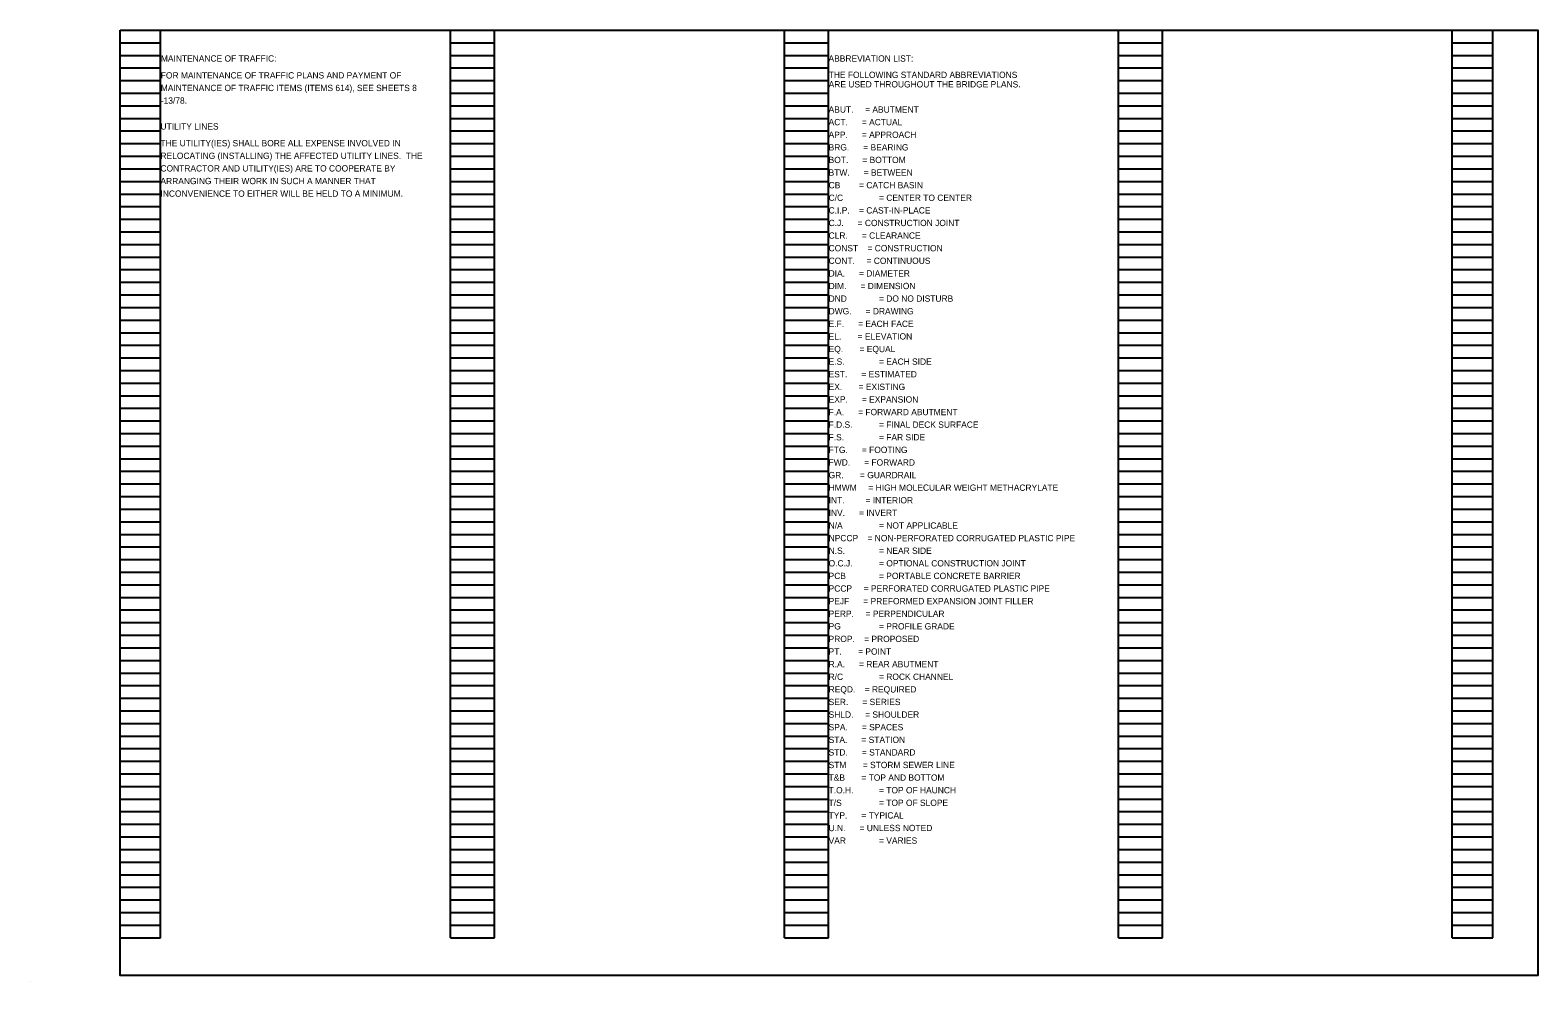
# Model space of a CAD drawing. Extents: x 8.9 to 72, y -18.6 to 3.4.
# Drawn here: x 8.86 to 42.36, y -18.57 to 2.57 of the extents above; entities that cross this region are included whole.
import ezdxf

# ---------------------------------------------------------------- set-up
doc = ezdxf.new("R2010")
doc.units = 0
for name, color, linetype in [('BR_P_Gen_Text', 7, 'Continuous'), ('Default', 7, 'Continuous'), ('SC_Scratch1', 7, 'Continuous'), ('SH_Data', 7, 'Continuous')]:
    doc.layers.add(name, color=color, linetype=linetype)

msp = doc.modelspace()

# ---------------------------------------------------------------- linework, layer by layer
at = {"layer": 'SC_Scratch1'}
msp.add_lwpolyline([(10.858, 2.575), (42.358, 2.575), (42.358, -18.425), (10.858, -18.425)], close=True, dxfattribs=at)
at = {"layer": 'SH_Data'}
for p, q in [((10.858, -17.585), (10.858, 2.575)), ((10.858, 2.575), (11.758, 2.575)), ((11.758, -17.585), (11.758, 2.575)), ((18.198, -17.585), (18.198, 2.575)), ((18.198, 2.575), (19.178, 2.575)), ((19.178, -17.585), (19.178, 2.575)), ((25.618, -17.585), (25.618, 2.575)), ((25.618, 2.575), (26.598, 2.575)), ((26.598, -17.585), (26.598, 2.575)), ((33.038, -17.585), (33.038, 2.575)), ((33.038, 2.575), (34.018, 2.575)), ((34.018, -17.585), (34.018, 2.575)), ((40.458, -17.585), (40.458, 2.575)), ((40.458, 2.575), (41.358, 2.575)), ((41.358, -17.585), (41.358, 2.575)), ((10.858, 2.295), (11.758, 2.295)), ((10.858, 2.015), (11.758, 2.015)), ((18.198, 2.295), (19.178, 2.295)), ((18.198, 2.015), (19.178, 2.015)), ((25.618, 2.295), (26.598, 2.295)), ((25.618, 2.015), (26.598, 2.015)), ((33.038, 2.295), (34.018, 2.295)), ((33.038, 2.015), (34.018, 2.015)), ((40.458, 2.295), (41.358, 2.295)), ((40.458, 2.015), (41.358, 2.015)), ((10.858, 1.735), (11.758, 1.735)), ((18.198, 1.735), (19.178, 1.735)), ((25.618, 1.735), (26.598, 1.735)), ((33.038, 1.735), (34.018, 1.735)), ((40.458, 1.735), (41.358, 1.735)), ((10.858, 1.455), (11.758, 1.455)), ((18.198, 1.455), (19.178, 1.455)), ((25.618, 1.455), (26.598, 1.455)), ((33.038, 1.455), (34.018, 1.455)), ((40.458, 1.455), (41.358, 1.455)), ((10.858, 1.175), (11.758, 1.175)), ((18.198, 1.175), (19.178, 1.175)), ((25.618, 1.175), (26.598, 1.175)), ((33.038, 1.175), (34.018, 1.175)), ((40.458, 1.175), (41.358, 1.175)), ((10.858, 0.895), (11.758, 0.895)), ((18.198, 0.895), (19.178, 0.895)), ((25.618, 0.895), (26.598, 0.895)), ((33.038, 0.895), (34.018, 0.895)), ((40.458, 0.895), (41.358, 0.895)), ((10.858, 0.615), (11.758, 0.615)), ((18.198, 0.615), (19.178, 0.615)), ((25.618, 0.615), (26.598, 0.615)), ((33.038, 0.615), (34.018, 0.615)), ((40.458, 0.615), (41.358, 0.615)), ((10.858, 0.335), (11.758, 0.335)), ((10.858, 0.055), (11.758, 0.055)), ((18.198, 0.335), (19.178, 0.335)), ((18.198, 0.055), (19.178, 0.055)), ((25.618, 0.335), (26.598, 0.335)), ((25.618, 0.055), (26.598, 0.055)), ((33.038, 0.335), (34.018, 0.335)), ((33.038, 0.055), (34.018, 0.055)), ((40.458, 0.335), (41.358, 0.335)), ((40.458, 0.055), (41.358, 0.055)), ((10.858, -0.225), (11.758, -0.225)), ((18.198, -0.225), (19.178, -0.225)), ((25.618, -0.225), (26.598, -0.225)), ((33.038, -0.225), (34.018, -0.225)), ((40.458, -0.225), (41.358, -0.225)), ((10.858, -0.505), (11.758, -0.505)), ((18.198, -0.505), (19.178, -0.505)), ((25.618, -0.505), (26.598, -0.505)), ((33.038, -0.505), (34.018, -0.505)), ((40.458, -0.505), (41.358, -0.505)), ((10.858, -0.785), (11.758, -0.785)), ((18.198, -0.785), (19.178, -0.785)), ((25.618, -0.785), (26.598, -0.785)), ((33.038, -0.785), (34.018, -0.785)), ((40.458, -0.785), (41.358, -0.785)), ((10.858, -1.065), (11.758, -1.065)), ((18.198, -1.065), (19.178, -1.065)), ((25.618, -1.065), (26.598, -1.065)), ((33.038, -1.065), (34.018, -1.065)), ((40.458, -1.065), (41.358, -1.065)), ((10.858, -1.345), (11.758, -1.345)), ((10.858, -1.625), (11.758, -1.625)), ((18.198, -1.345), (19.178, -1.345)), ((18.198, -1.625), (19.178, -1.625)), ((25.618, -1.345), (26.598, -1.345)), ((25.618, -1.625), (26.598, -1.625)), ((33.038, -1.345), (34.018, -1.345)), ((33.038, -1.625), (34.018, -1.625)), ((40.458, -1.345), (41.358, -1.345)), ((40.458, -1.625), (41.358, -1.625)), ((10.858, -1.905), (11.758, -1.905)), ((18.198, -1.905), (19.178, -1.905)), ((25.618, -1.905), (26.598, -1.905)), ((33.038, -1.905), (34.018, -1.905)), ((40.458, -1.905), (41.358, -1.905)), ((10.858, -2.185), (11.758, -2.185)), ((18.198, -2.185), (19.178, -2.185)), ((25.618, -2.185), (26.598, -2.185)), ((33.038, -2.185), (34.018, -2.185)), ((40.458, -2.185), (41.358, -2.185)), ((10.858, -2.465), (11.758, -2.465)), ((18.198, -2.465), (19.178, -2.465)), ((25.618, -2.465), (26.598, -2.465)), ((33.038, -2.465), (34.018, -2.465)), ((40.458, -2.465), (41.358, -2.465)), ((10.858, -2.745), (11.758, -2.745)), ((18.198, -2.745), (19.178, -2.745)), ((25.618, -2.745), (26.598, -2.745)), ((33.038, -2.745), (34.018, -2.745)), ((40.458, -2.745), (41.358, -2.745)), ((10.858, -3.025), (11.758, -3.025)), ((10.858, -3.305), (11.758, -3.305)), ((18.198, -3.025), (19.178, -3.025)), ((18.198, -3.305), (19.178, -3.305)), ((25.618, -3.025), (26.598, -3.025)), ((25.618, -3.305), (26.598, -3.305)), ((33.038, -3.025), (34.018, -3.025)), ((33.038, -3.305), (34.018, -3.305)), ((40.458, -3.025), (41.358, -3.025)), ((40.458, -3.305), (41.358, -3.305)), ((10.858, -3.585), (11.758, -3.585)), ((18.198, -3.585), (19.178, -3.585)), ((25.618, -3.585), (26.598, -3.585)), ((33.038, -3.585), (34.018, -3.585)), ((40.458, -3.585), (41.358, -3.585)), ((10.858, -3.865), (11.758, -3.865)), ((18.198, -3.865), (19.178, -3.865)), ((25.618, -3.865), (26.598, -3.865)), ((33.038, -3.865), (34.018, -3.865)), ((40.458, -3.865), (41.358, -3.865)), ((10.858, -4.145), (11.758, -4.145)), ((18.198, -4.145), (19.178, -4.145)), ((25.618, -4.145), (26.598, -4.145)), ((33.038, -4.145), (34.018, -4.145)), ((40.458, -4.145), (41.358, -4.145)), ((10.858, -4.425), (11.758, -4.425)), ((18.198, -4.425), (19.178, -4.425)), ((25.618, -4.425), (26.598, -4.425)), ((33.038, -4.425), (34.018, -4.425)), ((40.458, -4.425), (41.358, -4.425)), ((10.858, -4.705), (11.758, -4.705)), ((10.858, -4.985), (11.758, -4.985)), ((18.198, -4.705), (19.178, -4.705)), ((18.198, -4.985), (19.178, -4.985)), ((25.618, -4.705), (26.598, -4.705)), ((25.618, -4.985), (26.598, -4.985)), ((33.038, -4.705), (34.018, -4.705)), ((33.038, -4.985), (34.018, -4.985)), ((40.458, -4.705), (41.358, -4.705)), ((40.458, -4.985), (41.358, -4.985)), ((10.858, -5.265), (11.758, -5.265)), ((18.198, -5.265), (19.178, -5.265)), ((25.618, -5.265), (26.598, -5.265)), ((33.038, -5.265), (34.018, -5.265)), ((40.458, -5.265), (41.358, -5.265)), ((10.858, -5.545), (11.758, -5.545)), ((18.198, -5.545), (19.178, -5.545)), ((25.618, -5.545), (26.598, -5.545)), ((33.038, -5.545), (34.018, -5.545)), ((40.458, -5.545), (41.358, -5.545)), ((10.858, -5.825), (11.758, -5.825)), ((18.198, -5.825), (19.178, -5.825)), ((25.618, -5.825), (26.598, -5.825)), ((33.038, -5.825), (34.018, -5.825)), ((40.458, -5.825), (41.358, -5.825)), ((10.858, -6.105), (11.758, -6.105)), ((18.198, -6.105), (19.178, -6.105)), ((25.618, -6.105), (26.598, -6.105)), ((33.038, -6.105), (34.018, -6.105)), ((40.458, -6.105), (41.358, -6.105)), ((10.858, -6.385), (11.758, -6.385)), ((10.858, -6.665), (11.758, -6.665)), ((18.198, -6.385), (19.178, -6.385)), ((18.198, -6.665), (19.178, -6.665)), ((25.618, -6.385), (26.598, -6.385)), ((25.618, -6.665), (26.598, -6.665)), ((33.038, -6.385), (34.018, -6.385)), ((33.038, -6.665), (34.018, -6.665)), ((40.458, -6.385), (41.358, -6.385)), ((40.458, -6.665), (41.358, -6.665)), ((10.858, -6.945), (11.758, -6.945)), ((18.198, -6.945), (19.178, -6.945)), ((25.618, -6.945), (26.598, -6.945)), ((33.038, -6.945), (34.018, -6.945)), ((40.458, -6.945), (41.358, -6.945)), ((10.858, -7.225), (11.758, -7.225)), ((18.198, -7.225), (19.178, -7.225)), ((25.618, -7.225), (26.598, -7.225)), ((33.038, -7.225), (34.018, -7.225)), ((40.458, -7.225), (41.358, -7.225)), ((10.858, -7.505), (11.758, -7.505)), ((18.198, -7.505), (19.178, -7.505)), ((25.618, -7.505), (26.598, -7.505)), ((33.038, -7.505), (34.018, -7.505)), ((40.458, -7.505), (41.358, -7.505)), ((10.858, -7.785), (11.758, -7.785)), ((18.198, -7.785), (19.178, -7.785)), ((25.618, -7.785), (26.598, -7.785)), ((33.038, -7.785), (34.018, -7.785)), ((40.458, -7.785), (41.358, -7.785)), ((10.858, -8.065), (11.758, -8.065)), ((10.858, -8.345), (11.758, -8.345)), ((18.198, -8.065), (19.178, -8.065)), ((18.198, -8.345), (19.178, -8.345)), ((25.618, -8.065), (26.598, -8.065)), ((25.618, -8.345), (26.598, -8.345)), ((33.038, -8.065), (34.018, -8.065)), ((33.038, -8.345), (34.018, -8.345)), ((40.458, -8.065), (41.358, -8.065)), ((40.458, -8.345), (41.358, -8.345)), ((10.858, -8.625), (11.758, -8.625)), ((18.198, -8.625), (19.178, -8.625)), ((25.618, -8.625), (26.598, -8.625)), ((33.038, -8.625), (34.018, -8.625)), ((40.458, -8.625), (41.358, -8.625)), ((10.858, -8.905), (11.758, -8.905)), ((18.198, -8.905), (19.178, -8.905)), ((25.618, -8.905), (26.598, -8.905)), ((33.038, -8.905), (34.018, -8.905)), ((40.458, -8.905), (41.358, -8.905)), ((10.858, -9.185), (11.758, -9.185)), ((18.198, -9.185), (19.178, -9.185)), ((25.618, -9.185), (26.598, -9.185)), ((33.038, -9.185), (34.018, -9.185)), ((40.458, -9.185), (41.358, -9.185)), ((10.858, -9.465), (11.758, -9.465)), ((18.198, -9.465), (19.178, -9.465)), ((25.618, -9.465), (26.598, -9.465)), ((33.038, -9.465), (34.018, -9.465)), ((40.458, -9.465), (41.358, -9.465)), ((10.858, -9.745), (11.758, -9.745)), ((10.858, -10.025), (11.758, -10.025)), ((18.198, -9.745), (19.178, -9.745)), ((18.198, -10.025), (19.178, -10.025)), ((25.618, -9.745), (26.598, -9.745)), ((25.618, -10.025), (26.598, -10.025)), ((33.038, -9.745), (34.018, -9.745)), ((33.038, -10.025), (34.018, -10.025)), ((40.458, -9.745), (41.358, -9.745)), ((40.458, -10.025), (41.358, -10.025)), ((10.858, -10.305), (11.758, -10.305)), ((18.198, -10.305), (19.178, -10.305)), ((25.618, -10.305), (26.598, -10.305)), ((33.038, -10.305), (34.018, -10.305)), ((40.458, -10.305), (41.358, -10.305)), ((10.858, -10.585), (11.758, -10.585)), ((18.198, -10.585), (19.178, -10.585)), ((25.618, -10.585), (26.598, -10.585)), ((33.038, -10.585), (34.018, -10.585)), ((40.458, -10.585), (41.358, -10.585)), ((10.858, -10.865), (11.758, -10.865)), ((18.198, -10.865), (19.178, -10.865)), ((25.618, -10.865), (26.598, -10.865)), ((33.038, -10.865), (34.018, -10.865)), ((40.458, -10.865), (41.358, -10.865)), ((10.858, -11.145), (11.758, -11.145)), ((18.198, -11.145), (19.178, -11.145)), ((25.618, -11.145), (26.598, -11.145)), ((33.038, -11.145), (34.018, -11.145)), ((40.458, -11.145), (41.358, -11.145)), ((10.858, -11.425), (11.758, -11.425)), ((10.858, -11.705), (11.758, -11.705)), ((18.198, -11.425), (19.178, -11.425)), ((18.198, -11.705), (19.178, -11.705)), ((25.618, -11.425), (26.598, -11.425)), ((25.618, -11.705), (26.598, -11.705)), ((33.038, -11.425), (34.018, -11.425)), ((33.038, -11.705), (34.018, -11.705)), ((40.458, -11.425), (41.358, -11.425)), ((40.458, -11.705), (41.358, -11.705)), ((10.858, -11.985), (11.758, -11.985)), ((18.198, -11.985), (19.178, -11.985)), ((25.618, -11.985), (26.598, -11.985)), ((33.038, -11.985), (34.018, -11.985)), ((40.458, -11.985), (41.358, -11.985)), ((10.858, -12.265), (11.758, -12.265)), ((18.198, -12.265), (19.178, -12.265)), ((25.618, -12.265), (26.598, -12.265)), ((33.038, -12.265), (34.018, -12.265)), ((40.458, -12.265), (41.358, -12.265)), ((10.858, -12.545), (11.758, -12.545)), ((18.198, -12.545), (19.178, -12.545)), ((25.618, -12.545), (26.598, -12.545)), ((33.038, -12.545), (34.018, -12.545)), ((40.458, -12.545), (41.358, -12.545)), ((10.858, -12.825), (11.758, -12.825)), ((18.198, -12.825), (19.178, -12.825)), ((25.618, -12.825), (26.598, -12.825)), ((33.038, -12.825), (34.018, -12.825)), ((40.458, -12.825), (41.358, -12.825)), ((10.858, -13.105), (11.758, -13.105)), ((10.858, -13.385), (11.758, -13.385)), ((18.198, -13.105), (19.178, -13.105)), ((18.198, -13.385), (19.178, -13.385)), ((25.618, -13.105), (26.598, -13.105)), ((25.618, -13.385), (26.598, -13.385)), ((33.038, -13.105), (34.018, -13.105)), ((33.038, -13.385), (34.018, -13.385)), ((40.458, -13.105), (41.358, -13.105)), ((40.458, -13.385), (41.358, -13.385)), ((10.858, -13.665), (11.758, -13.665)), ((18.198, -13.665), (19.178, -13.665)), ((25.618, -13.665), (26.598, -13.665)), ((33.038, -13.665), (34.018, -13.665)), ((40.458, -13.665), (41.358, -13.665)), ((10.858, -13.945), (11.758, -13.945)), ((18.198, -13.945), (19.178, -13.945)), ((25.618, -13.945), (26.598, -13.945)), ((33.038, -13.945), (34.018, -13.945)), ((40.458, -13.945), (41.358, -13.945)), ((10.858, -14.225), (11.758, -14.225)), ((18.198, -14.225), (19.178, -14.225)), ((25.618, -14.225), (26.598, -14.225)), ((33.038, -14.225), (34.018, -14.225)), ((40.458, -14.225), (41.358, -14.225)), ((10.858, -14.505), (11.758, -14.505)), ((18.198, -14.505), (19.178, -14.505)), ((25.618, -14.505), (26.598, -14.505)), ((33.038, -14.505), (34.018, -14.505)), ((40.458, -14.505), (41.358, -14.505)), ((10.858, -14.785), (11.758, -14.785)), ((10.858, -15.065), (11.758, -15.065)), ((18.198, -14.785), (19.178, -14.785)), ((18.198, -15.065), (19.178, -15.065)), ((25.618, -14.785), (26.598, -14.785)), ((25.618, -15.065), (26.598, -15.065)), ((33.038, -14.785), (34.018, -14.785)), ((33.038, -15.065), (34.018, -15.065)), ((40.458, -14.785), (41.358, -14.785)), ((40.458, -15.065), (41.358, -15.065)), ((10.858, -15.345), (11.758, -15.345)), ((18.198, -15.345), (19.178, -15.345)), ((25.618, -15.345), (26.598, -15.345)), ((33.038, -15.345), (34.018, -15.345)), ((40.458, -15.345), (41.358, -15.345)), ((10.858, -15.625), (11.758, -15.625)), ((18.198, -15.625), (19.178, -15.625)), ((25.618, -15.625), (26.598, -15.625)), ((33.038, -15.625), (34.018, -15.625)), ((40.458, -15.625), (41.358, -15.625)), ((10.858, -15.905), (11.758, -15.905)), ((18.198, -15.905), (19.178, -15.905)), ((25.618, -15.905), (26.598, -15.905)), ((33.038, -15.905), (34.018, -15.905)), ((40.458, -15.905), (41.358, -15.905)), ((10.858, -16.185), (11.758, -16.185)), ((18.198, -16.185), (19.178, -16.185)), ((25.618, -16.185), (26.598, -16.185)), ((33.038, -16.185), (34.018, -16.185)), ((40.458, -16.185), (41.358, -16.185)), ((10.858, -16.465), (11.758, -16.465)), ((10.858, -16.745), (11.758, -16.745)), ((18.198, -16.465), (19.178, -16.465)), ((18.198, -16.745), (19.178, -16.745)), ((25.618, -16.465), (26.598, -16.465)), ((25.618, -16.745), (26.598, -16.745)), ((33.038, -16.465), (34.018, -16.465)), ((33.038, -16.745), (34.018, -16.745)), ((40.458, -16.465), (41.358, -16.465)), ((40.458, -16.745), (41.358, -16.745)), ((10.858, -17.025), (11.758, -17.025)), ((18.198, -17.025), (19.178, -17.025)), ((25.618, -17.025), (26.598, -17.025)), ((33.038, -17.025), (34.018, -17.025)), ((40.458, -17.025), (41.358, -17.025)), ((10.858, -17.305), (11.758, -17.305)), ((18.198, -17.305), (19.178, -17.305)), ((25.618, -17.305), (26.598, -17.305)), ((33.038, -17.305), (34.018, -17.305)), ((40.458, -17.305), (41.358, -17.305)), ((10.858, -17.585), (11.758, -17.585)), ((18.198, -17.585), (19.178, -17.585)), ((25.618, -17.585), (26.598, -17.585)), ((33.038, -17.585), (34.018, -17.585)), ((40.458, -17.585), (41.358, -17.585)), ((8.858, -18.565), (8.858, -18.565))]:
    msp.add_line(p, q, dxfattribs=at)

# ---------------------------------------------------------------- texts
at = {"layer": 'BR_P_Gen_Text'}
for s, p in [('MAINTENANCE OF TRAFFIC:', (11.763, 1.876)), ('ABBREVIATION LIST:', (26.598, 1.875)), ('FOR MAINTENANCE OF TRAFFIC PLANS AND PAYMENT OF ', (11.761, 1.501)), ('MAINTENANCE OF TRAFFIC ITEMS (ITEMS 614), SEE SHEETS 8', (11.761, 1.221)), ('ARE USED THROUGHOUT THE BRIDGE PLANS.', (26.601, 1.302)), ('THE FOLLOWING STANDARD ABBREVIATIONS', (26.601, 1.512)), ('-13/78.', (11.761, 0.941))]:
    msp.add_text(s, height=0.14, dxfattribs=at).set_placement(p)
for s, p in [('UTILITY LINES', (11.755, 0.367)), ('THE UTILITY(IES) SHALL BORE ALL EXPENSE INVOLVED IN ', (11.754, -0.005)), ('RELOCATING (INSTALLING) THE AFFECTED UTILITY LINES.  THE ', (11.754, -0.285)), ('CONTRACTOR AND UTILITY(IES) ARE TO COOPERATE BY ', (11.754, -0.565)), ('ARRANGING THEIR WORK IN SUCH A MANNER THAT ', (11.754, -0.846)), ('INCONVENIENCE TO EITHER WILL BE HELD TO A MINIMUM.', (11.754, -1.126))]:
    msp.add_text(s, height=0.14, rotation=0, dxfattribs=at).set_placement(p)
at = {"layer": 'Default'}
for s, p in [('ABUT.     = ABUTMENT', (26.6, 0.742)), ('ACT.      = ACTUAL', (26.6, 0.462)), ('APP.      = APPROACH', (26.6, 0.182)), ('BRG.      = BEARING', (26.6, -0.098)), ('BOT.      = BOTTOM', (26.6, -0.378)), ('BTW.      = BETWEEN', (26.6, -0.658)), ('CB        = CATCH BASIN', (26.6, -0.938)), ('C/C', (26.6, -1.218)), ('= CENTER TO CENTER', (27.72, -1.218)), ('C.I.P.    = CAST-IN-PLACE', (26.6, -1.498)), ('C.J.      = CONSTRUCTION JOINT', (26.6, -1.778)), ('CLR.      = CLEARANCE', (26.6, -2.058)), ('CONST    = CONSTRUCTION', (26.6, -2.338)), ('CONT.     = CONTINUOUS', (26.6, -2.618)), ('DIA.      = DIAMETER', (26.6, -2.898)), ('DIM.      = DIMENSION', (26.6, -3.178)), ('DND', (26.6, -3.458)), ('= DO NO DISTURB', (27.72, -3.458)), ('DWG.      = DRAWING', (26.6, -3.738)), ('E.F.      = EACH FACE', (26.6, -4.018)), ('EL.       = ELEVATION', (26.6, -4.298)), ('EQ.       = EQUAL', (26.6, -4.578)), ('E.S.', (26.6, -4.858)), ('EST.      = ESTIMATED', (26.6, -5.138)), ('= EACH SIDE', (27.72, -4.858)), ('EX.       = EXISTING', (26.6, -5.418)), ('EXP.      = EXPANSION', (26.6, -5.698)), ('F.A.      = FORWARD ABUTMENT', (26.6, -5.978)), ('F.D.S.', (26.6, -6.258)), ('= FINAL DECK SURFACE', (27.72, -6.258)), ('F.S.  ', (26.6, -6.538)), ('FTG.      = FOOTING', (26.6, -6.818)), ('= FAR SIDE', (27.72, -6.538)), ('FWD.      = FORWARD', (26.6, -7.098)), ('GR.       = GUARDRAIL', (26.6, -7.378)), ('HMWM     = HIGH MOLECULAR WEIGHT METHACRYLATE', (26.6, -7.658)), ('INT.', (26.6, -7.938)), ('     = INTERIOR', (27.16, -7.938)), ('N/A', (26.6, -8.498)), ('INV.      = INVERT', (26.6, -8.218)), ('= NOT APPLICABLE', (27.72, -8.498)), ('NPCCP    = NON-PERFORATED CORRUGATED PLASTIC PIPE', (26.6, -8.778)), ('N.S.', (26.6, -9.058)), ('= NEAR SIDE', (27.72, -9.058)), ('O.C.J.', (26.6, -9.338)), ('= OPTIONAL CONSTRUCTION JOINT', (27.72, -9.338)), ('PCB', (26.6, -9.618)), ('= PORTABLE CONCRETE BARRIER', (27.72, -9.618)), ('PCCP     = PERFORATED CORRUGATED PLASTIC PIPE', (26.6, -9.898)), ('PEJF      = PREFORMED EXPANSION JOINT FILLER', (26.6, -10.178)), ('PERP.     = PERPENDICULAR', (26.6, -10.458)), ('PG', (26.6, -10.738)), ('= PROFILE GRADE', (27.72, -10.738)), ('PROP.    = PROPOSED', (26.6, -11.018)), ('PT.       = POINT', (26.6, -11.298)), ('R.A.      = REAR ABUTMENT', (26.6, -11.578)), ('R/C', (26.6, -11.858)), ('= ROCK CHANNEL', (27.72, -11.858)), ('REQD.    = REQUIRED', (26.6, -12.138)), ('SER.      = SERIES', (26.6, -12.418)), ('SHLD.     = SHOULDER', (26.6, -12.698)), ('SPA.      = SPACES', (26.6, -12.978)), ('STA.      = STATION', (26.6, -13.258)), ('STD.      = STANDARD', (26.6, -13.538)), ('STM       = STORM SEWER LINE', (26.6, -13.818)), ('T&B       = TOP AND BOTTOM', (26.6, -14.098)), ('T.O.H.', (26.6, -14.378)), ('= TOP OF HAUNCH', (27.72, -14.378)), ('T/S', (26.6, -14.658)), ('= TOP OF SLOPE', (27.72, -14.658)), ('TYP.      = TYPICAL', (26.6, -14.938)), ('VAR', (26.6, -15.498)), ('U.N.      = UNLESS NOTED', (26.6, -15.218)), ('= VARIES', (27.72, -15.498))]:
    msp.add_text(s, height=0.14, rotation=0, dxfattribs=at).set_placement(p)

doc.saveas('drawing.dxf')
